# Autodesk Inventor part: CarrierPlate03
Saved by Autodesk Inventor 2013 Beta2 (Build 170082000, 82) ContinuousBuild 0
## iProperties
Created: 2008-02
Part Number: CarrierPlate03
Document SubType Name: Modeling
Designer: grh
Density: 1 g/cm^3
Material: Generic
Author: grh
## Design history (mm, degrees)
sketch "Sketch1"
  geometry: L1 (48.514, 0)-(0, 0); L2 (0, 0)-(37.164, 31.184); L3 (8.424, 47.777)-(0, 0); C1 r 53.34 at (0, 0)
  constraints: 6 end point, 2 equal length, 1 centre point, 1 horizontal, 1 other
  dimensions: "BlankDiameter" = 106.68 diameter of C1; "PlanetRadius" = 48.514 distance of L1.start L1.end; "Angle1" = 40 deg angle of L2 L1; "Angle2" = 40 deg angle of L3 L2
extrude "Extrusion1" new body sketch "Sketch1" stored distance "d9" = 13.97; taper "d10" = 0 deg
node "Axis1"
node "Axis2"
node "Axis3"
node "Axis4"
body "Solid1"
